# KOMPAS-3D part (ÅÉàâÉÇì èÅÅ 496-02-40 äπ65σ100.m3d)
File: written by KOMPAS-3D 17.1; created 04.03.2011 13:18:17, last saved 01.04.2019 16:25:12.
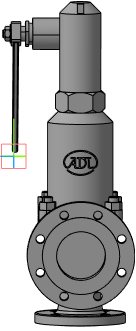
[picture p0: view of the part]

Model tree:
1. Плоскость XY
2. Плоскость ZX
3. Плоскость ZY
4. Ось X
5. Ось Y
6. Ось Z
7. Начало координат
8. Операция без истории:2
